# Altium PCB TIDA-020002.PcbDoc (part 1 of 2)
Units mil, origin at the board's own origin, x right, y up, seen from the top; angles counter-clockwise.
Board outline 1055.12 x 1877.5 mil, 6 copper layers (Layer 1 - Top Layer, Layer 2 - GND, Layer 3 - PWR, Layer 4 - Signal, Layer 5 - Signal/Gnd, Layer 6 - Bottom Layer), stack 62.2 mil thick; 103 components, 53 nets, 368 pads, 137 vias.
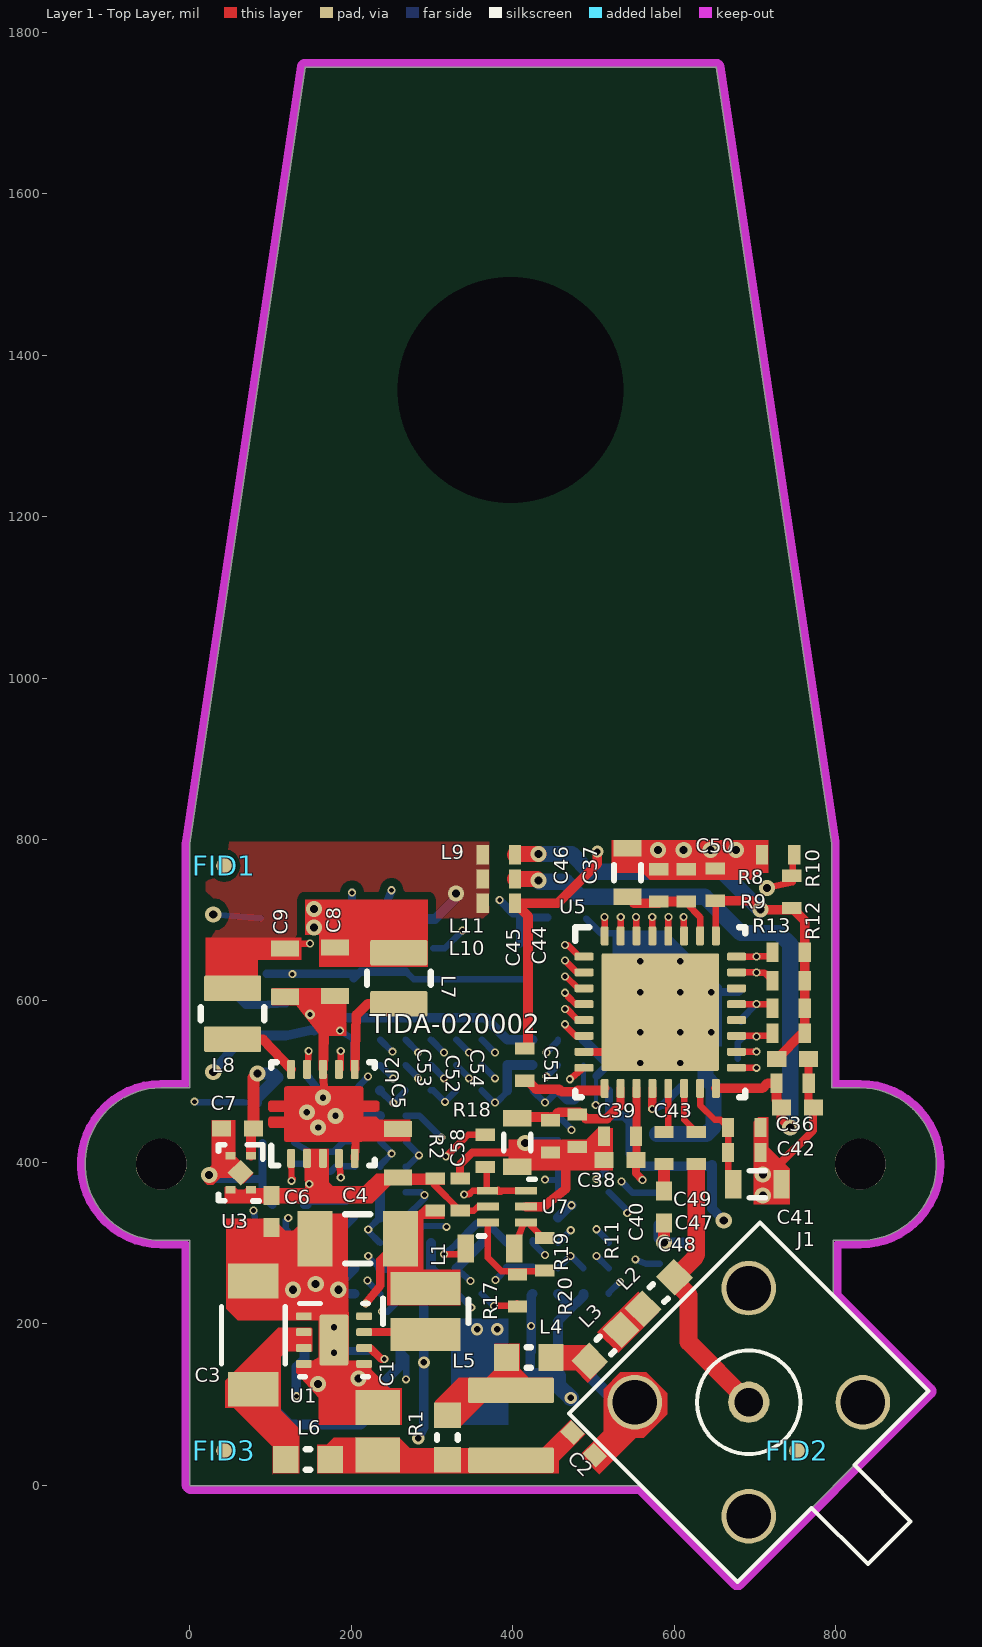
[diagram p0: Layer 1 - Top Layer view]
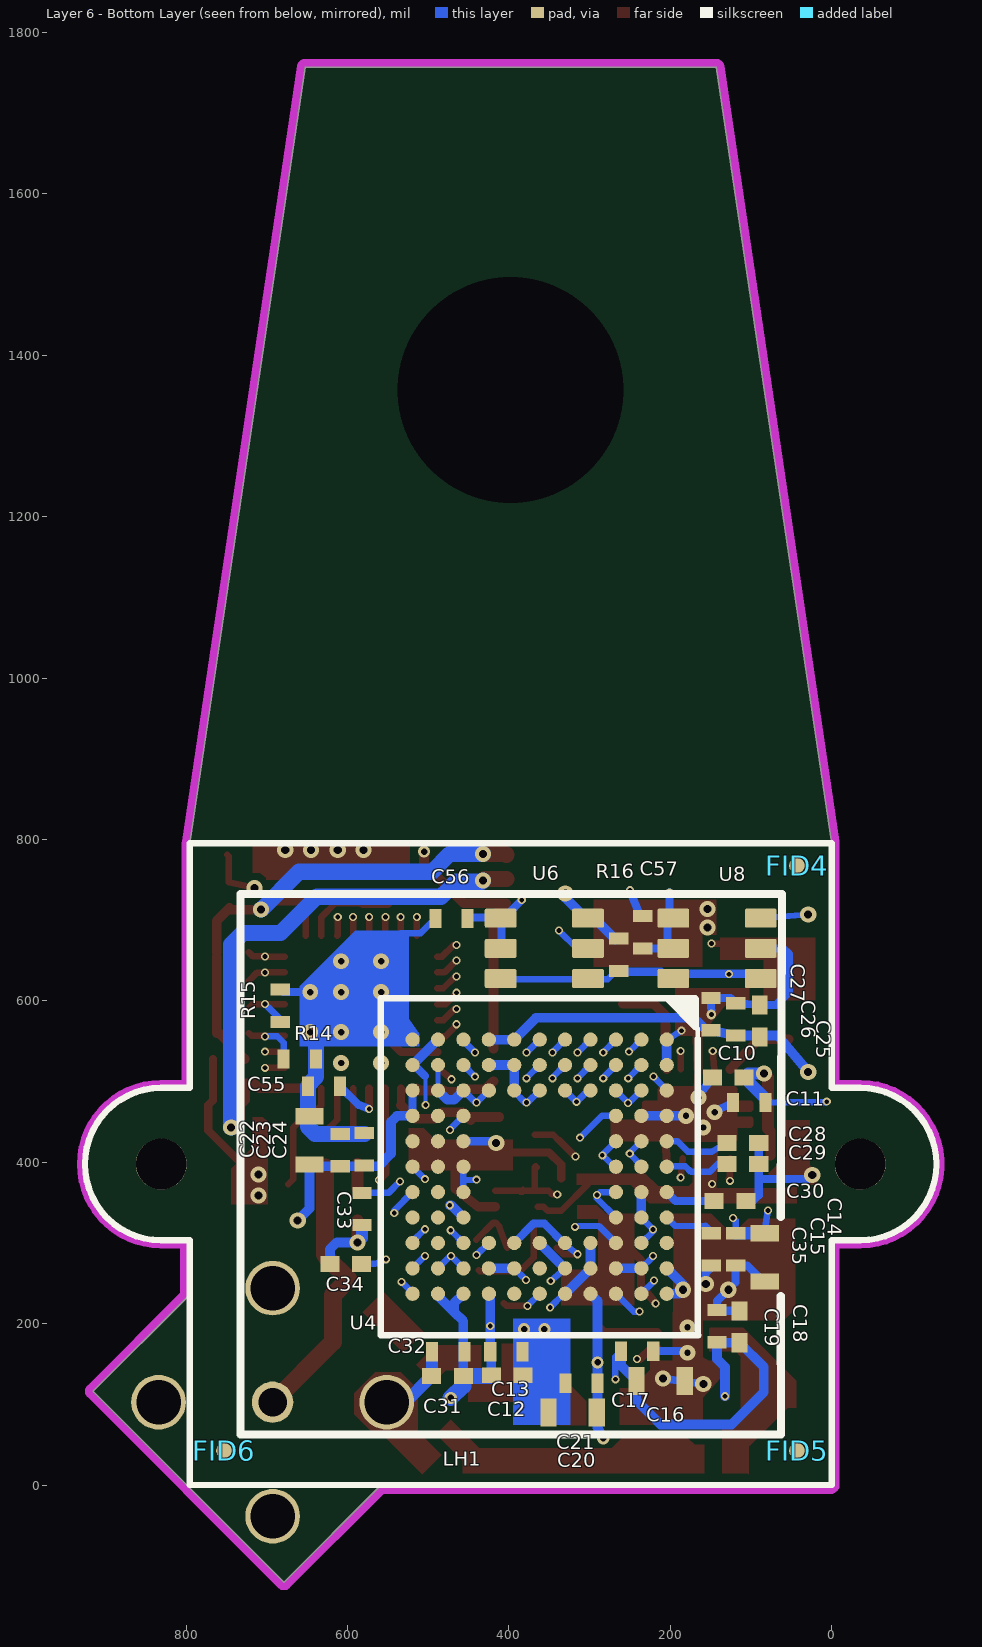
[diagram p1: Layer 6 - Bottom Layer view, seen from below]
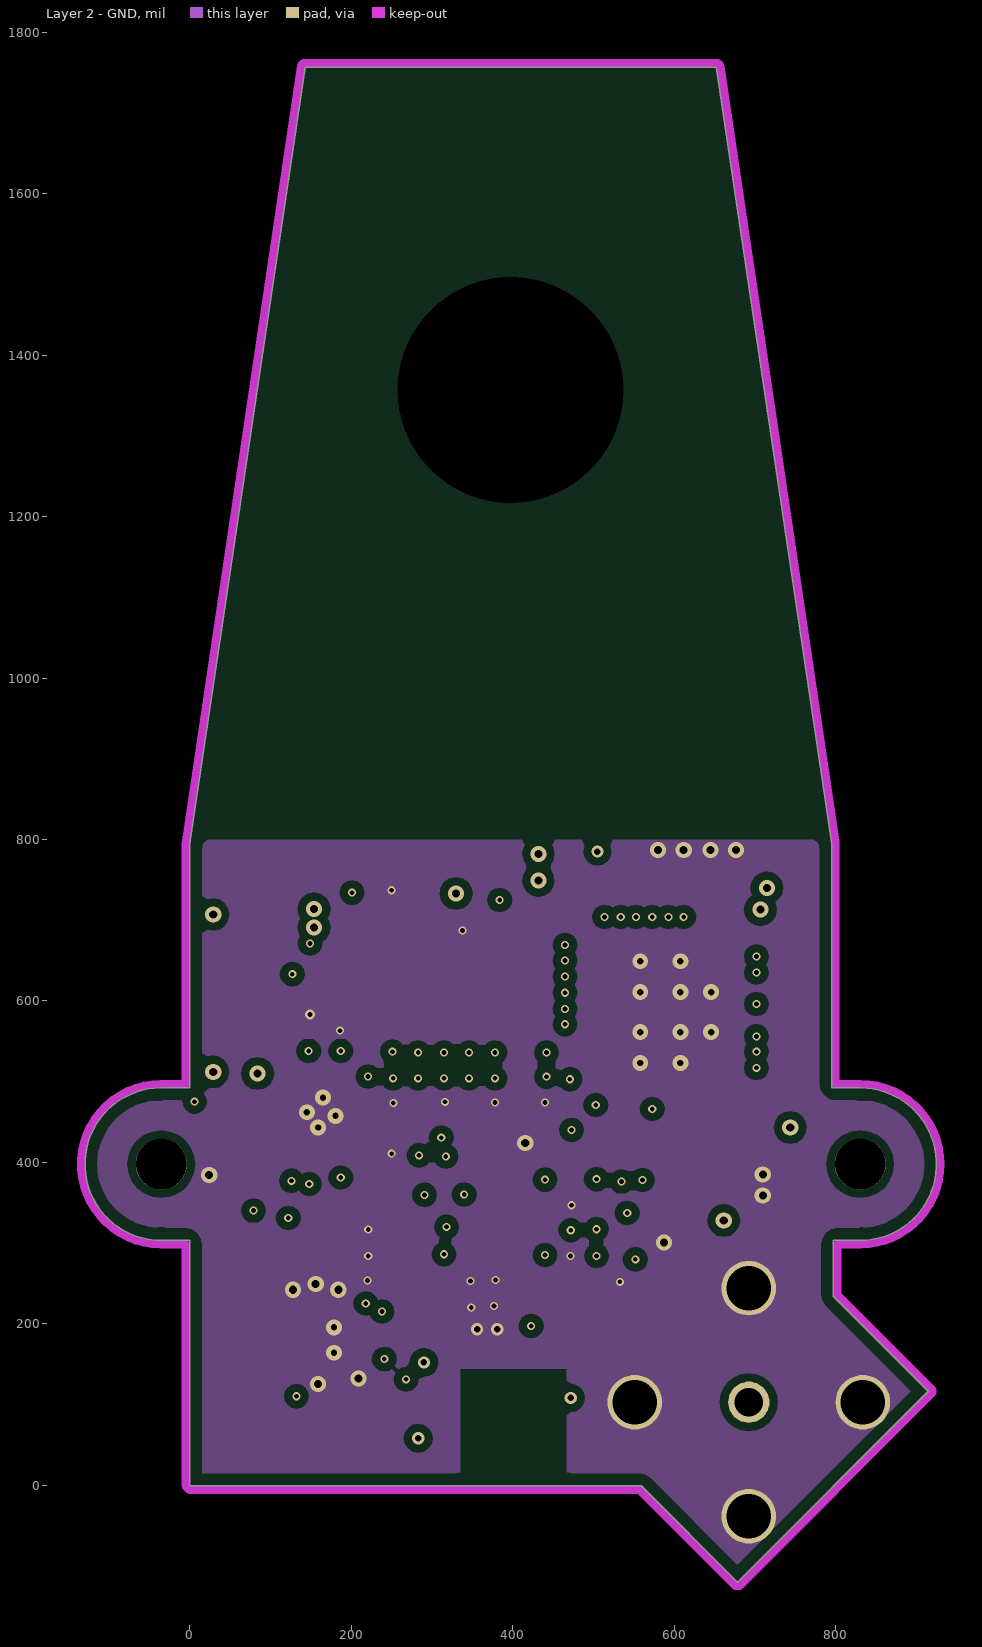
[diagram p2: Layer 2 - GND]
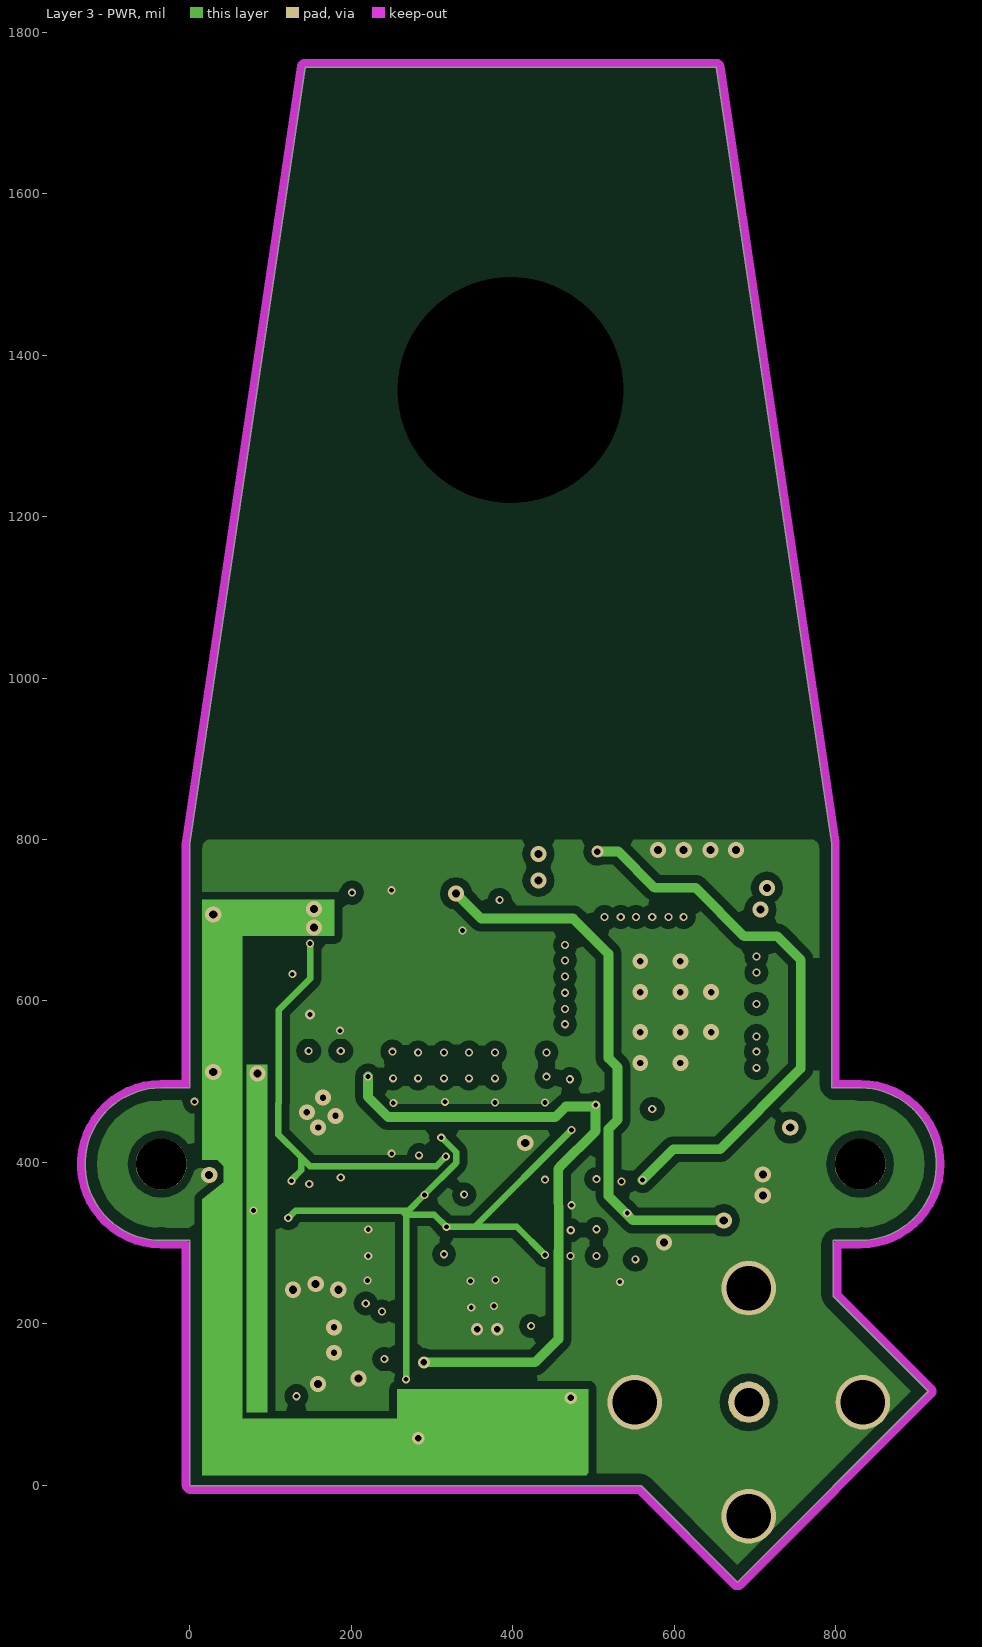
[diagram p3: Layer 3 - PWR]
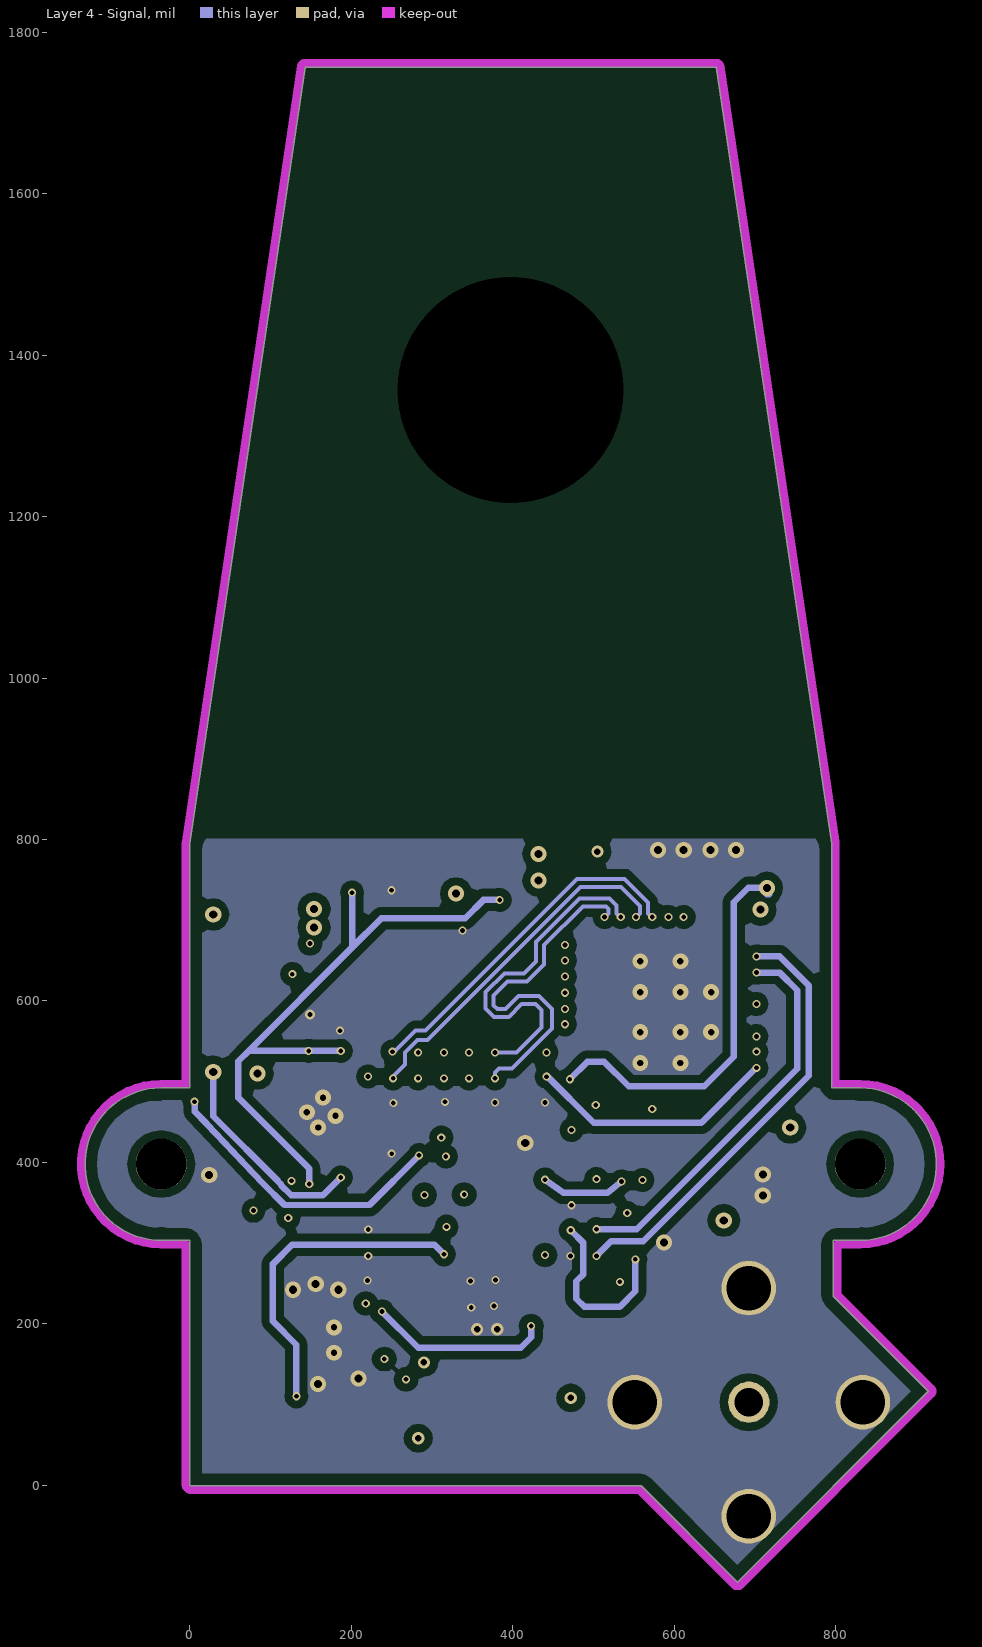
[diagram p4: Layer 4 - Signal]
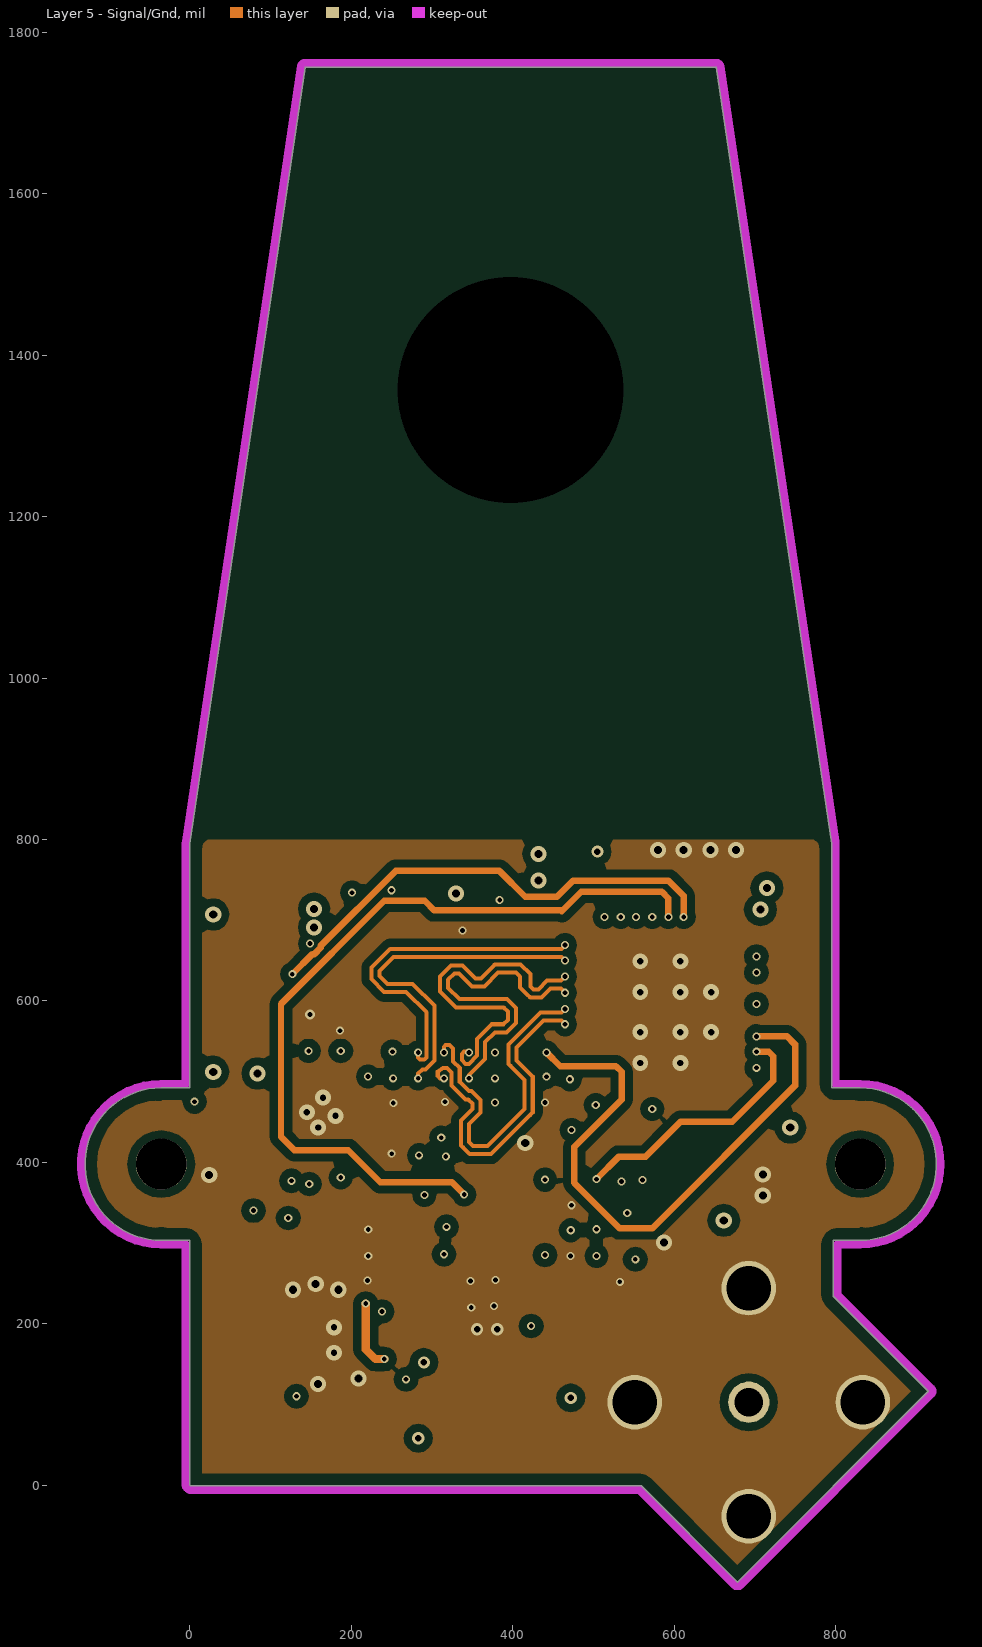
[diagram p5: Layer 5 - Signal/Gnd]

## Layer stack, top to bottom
Top Solder: solder mask 0.4, Solder Resist, Dk 3.5
Layer 1 - Top Layer: signal copper 1.4
Dielectric 1: prepreg 12.6, 370HR, Dk 4.2
Layer 2 - GND: signal copper 1.4
Dielectric 2: core 8, 370HR, Dk 4.2
Layer 3 - PWR: signal copper 1.4
Dielectric 5: prepreg 12.6, 370HR, Dk 4.2
Layer 4 - Signal: signal copper 1.4
Dielectric 4: core 8, 370HR, Dk 4.2
Layer 5 - Signal/Gnd: signal copper 1.4
Dielectric 3: prepreg 12.6, 370HR, Dk 4.2
Layer 6 - Bottom Layer: signal copper 1.4
Bottom Solder: solder mask 0.4, Solder Resist, Dk 3.5

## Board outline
-35.43,303.15 0,303.15 0,0 0.99,-0.99 559.27,-0.99 678.64,-120.36 915.14,116.14 797.27,234.01 797.27,303.15 830.71,303.15 ccw(c830.71,397.64) 830.71,492.13 795.28,492.13 795.28,795.28 795.28,794.64 652.39,1757.14 142.89,1757.14 0,794.64 0,795.28 0,492.13 -35.43,492.13 ccw(c-35.43,397.64)

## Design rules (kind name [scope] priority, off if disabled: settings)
AcuteAngle [All] p1 off: minimum=4.50000000000000E+0001 checktracksonly=FALSE
AssemblyTestPointUsage [All] p1: valid=2
Clearance Clearance_BoardEdge_MountingHoles [OnCopper and InComponentClass('Mounting Holes') vs IsKeepOut] p1 off: gap=30 ignorepadtopadclearanceinfootprint=FALSE except(0: Arc-Hole Track-Hole SMDPad-Hole THPad-Hole Via-Hole Fill-Hole Poly-Hole Region-Hole Text-Hole)
Clearance Clearance_BoardEdge_Poly [OnCopper and InPoly vs IsKeepOut] p2: gap=15 ignorepadtopadclearanceinfootprint=FALSE except(0: Arc-Hole Track-Hole SMDPad-Hole THPad-Hole Via-Hole Fill-Hole Poly-Hole Region-Hole Text-Hole)
Clearance Clearance_BoardEdge [OnCopper and Not InComponentClass('Logo') and not InComponentClass('FiducialMark') and not InRegion(1000,500,4000,800) and Not IsKeepout vs IsKeepOut and Not OnLayer('Keep-out Layer')] p3: gap=11 ignorepadtopadclearanceinfootprint=FALSE except(0: Arc-Hole Track-Hole SMDPad-Hole THPad-Hole Via-Hole Fill-Hole Poly-Hole Region-Hole Text-Hole)
Clearance Clearance_Poly [InPolygon] p4: gap=10 ignorepadtopadclearanceinfootprint=FALSE except(0: Arc-Hole Track-Hole SMDPad-Hole THPad-Hole Via-Hole Fill-Hole Poly-Hole Region-Hole Text-Hole)
Clearance [All] p5: gap=4 ignorepadtopadclearanceinfootprint=FALSE except(0: Arc-Hole Track-Hole SMDPad-Hole THPad-Hole Via-Hole Fill-Hole Poly-Hole Region-Hole Text-Hole)
ComponentClearance ComponentClearance_1 [issmtcomponent] p1: gap=0 collisioncheckmode=3 verticalgap=0 showdistances=FALSE
ComponentClearance ComponentClearance_Shunt [InComponentClass('Header') vs InComponentClass('Shunt')] p2: gap=0 collisioncheckmode=3 verticalgap=0 showdistances=FALSE
ComponentClearance ComponentClearance_Logo [InComponentClass('Logo')] p3: gap=0 collisioncheckmode=3 verticalgap=0 showdistances=FALSE
ComponentClearance ComponentClearance_ScrewToNut [(HasFootprint('NY PMS 440 0025 PH')) vs (HasFootprint('Keystone_1902C'))] p4: gap=5 collisioncheckmode=3 verticalgap=10 showdistances=FALSE
ComponentClearance ComponentClearance_MountingHoles [InComponentClass('Mounting Holes')] p5: gap=50 collisioncheckmode=3 verticalgap=50 showdistances=FALSE
ComponentClearance ComponentClearance_SmallPassives [HasFootprint('0201*') or HasFootprint('0402*') or HasFootprint('0508') or HasFootprint('0603*') or HasFootprint('0612') or HasFootprint('0805*') or HasFootprint('0815*') or HasFootprint('0830*') or HasFootprint('1206*') or HasFootprint('1210*') or HasFootprint('1808*') or HasFootprint('1812*') or HasFootprint('1825*') or HasFootprint('2010*') or HasFootprint('2220*') or HasFootprint('2225*') or HasFootprint('2512*') or HasFootprint('2728*') or HasFootprint('3518*') vs HasFootprint('0201*') or HasFootprint('0402*') or HasFootprint('0508') or HasFootprint('0603*') or HasFootprint('0612') or HasFootprint('0805*') or HasFootprint('0815*') or HasFootprint('0830*') or HasFootprint('1206*') or HasFootprint('1210*') or HasFootprint('1808*') or HasFootprint('1812*') or HasFootprint('1825*') or HasFootprint('2010*') or HasFootprint('2220*') or HasFootprint('2225*') or HasFootprint('2512*') or HasFootprint('2728*') or HasFootprint('3518*')] p6: gap=0 collisioncheckmode=3 verticalgap=0 showdistances=FALSE
ComponentClearance ComponentClearance_THtoSMT [IsThruComponent vs IsSMTComponent] p7: gap=0 collisioncheckmode=3 verticalgap=0 showdistances=FALSE
ComponentClearance ComponentClearance_THtoTH [IsThruComponent vs IsThruComponent] p8: gap=0 collisioncheckmode=3 verticalgap=0 showdistances=FALSE
ComponentClearance [All] p9: gap=0 collisioncheckmode=3 verticalgap=0 showdistances=FALSE
DiffPairsRouting DiffPair_Diff100_DiffPairsRouting [InDifferentialPairClass('Diff100')] p1: maxlimit=8 minlimit=5 mostfreqgap=8 toplayer_mingap=8 toplayer_minwidth=8 toplayer_maxwidth=8 toplayer_prefwidth=8 midlayer1_mingap=8 midlayer1_minwidth=8 midlayer1_maxwidth=8 midlayer1_prefwidth=8 midlayer2_mingap=8 midlayer2_minwidth=8 midlayer2_maxwidth=8 midlayer2_prefwidth=8 midlayer3_maxgap=5 midlayer3_prefgap=5 midlayer3_minwidth=5 midlayer3_maxwidth=5 midlayer3_prefwidth=5 midlayer4_maxgap=5 midlayer4_prefgap=5 midlayer4_minwidth=5 midlayer4_maxwidth=5 midlayer4_prefwidth=5 bottomlayer_mingap=8 bottomlayer_minwidth=8 bottomlayer_maxwidth=8 bottomlayer_prefwidth=8 maxuncoupledlength=500
DiffPairsRouting [All] p2: maxlimit=5 minlimit=5 mostfreqgap=5 toplayer_minwidth=5 toplayer_maxwidth=15 toplayer_prefwidth=8 midlayer1_minwidth=5 midlayer1_maxwidth=15 midlayer1_prefwidth=8 midlayer2_minwidth=5 midlayer2_maxwidth=15 midlayer2_prefwidth=8 midlayer3_minwidth=5 midlayer3_maxwidth=15 midlayer3_prefwidth=8 midlayer4_minwidth=5 midlayer4_maxwidth=15 midlayer4_prefwidth=8 bottomlayer_minwidth=5 bottomlayer_maxwidth=15 bottomlayer_prefwidth=8 maxuncoupledlength=1000
FabricationTestPointUsage TestPointUsage [All] p1: valid=2 allowmultiple=FALSE
FabricationTestpoint Testpoint [All] p1: side=3 testpointundercomponent=TRUE minsize=40 maxsize=100 preferedsize=60 minholesize=0 maxholesize=40 preferedholesize=32 testpointgrid=1 allowsidetop=TRUE allowsidebottom=TRUE usegrid=TRUE gridtolerance=0.01
FanoutControl Fanout_LCC [IsLCC] p1: bgadir=Out bgaviamode=Centered fanoutstyle=Auto fanoutdirection=Alternating viagrid=1 // Fanout_LCC (Default Rule)
FanoutControl Fanout_BGA [IsBGA] p2: bgadir=Out bgaviamode=Centered fanoutstyle=Auto fanoutdirection=Alternating viagrid=1 // Fanout_BGA (Default Rule)
FanoutControl Fanout_Default [All] p4: bgadir=Out bgaviamode=Centered fanoutstyle=Auto fanoutdirection=Alternating viagrid=1 // Fanout_Default (Default Rule)
FanoutControl Fanout_Small [(CompPinCount < 5)] p5: bgadir=Out bgaviamode=Centered fanoutstyle=Auto fanoutdirection=OutThenIn viagrid=1 // Fanout_Small (Default Rule)
HoleSize [All] p1: absolutevalues=TRUE maxlimit=280 minlimit=6 maxpercent=80.000 minpercent=20.000
MatchedLengths DiffPair_Diff100_MatchedLengths [InDifferentialPairClass('Diff100')] p1: tolerance=25 checknetsindiffpair=FALSE checkdiffpairvsdiffpair=TRUE checkxsignals=TRUE checkothers=TRUE
MinimumAnnularRing MinimumAnnularRing_ThermalPadVias [IsVia and InAnyComponent] p1: minimumring=5.91
MinimumAnnularRing [All] p2: minimumring=2
MinimumSolderMaskSliver MinimumSolderMaskSliver_Logo [InComponentClass('Logo') vs InComponentClass('Logo')] p1: minsoldermaskwidth=0.7
MinimumSolderMaskSliver [All] p2: minsoldermaskwidth=3.94
PlaneConnect [All] p1: planeconnectstyle=Relief reliefexpansion=10 reliefentries=4 reliefconductorwidth=10 reliefairgap=10
PolygonConnect [All] p1: connectstyle=Direct reliefconductorwidth=10 reliefentries=4 polygonreliefangle="90 Angle" airgapwidth=10
RoutingVias ThermalPadVias [IsVia and InAnyComponent] p1: holewidth=7.87 width=19.68 viastyle="Through Hole" minholewidth=7.87 minwidth=19.68 maxholewidth=12.99 maxwidth=23.62
RoutingVias [All] p2: holewidth=10 width=22 viastyle="Through Hole" minholewidth=6 minwidth=10 maxholewidth=40 maxwidth=65
SMDToCorner [All] p1: distance=25000
SilkToSilkClearance [All] p1: silktosilkclearance=0
SilkToSolderMaskClearance SilkscreenOverComponentPads [IsPad] p1: minsilkscreentomaskgap=0.2 clearancetoexposedcopper=TRUE
SolderMaskExpansion [All] p1: expansion=1
Width [All] p1: maxlimit=100 minlimit=5 preferedwidth=10 minimp=50.000000 maximp=50.000000 favimp=50.000000 checkconnectedcopper=TRUE
16 further rules are at their usual default settings.

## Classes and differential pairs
component class "Voltage Supervision": C56 C57 C58 R16 R17 R18 R19 R20 U6 U7 U8
differential pair class Diff100: CSI0_CLK CSI0_D0 CSI0_D1 CSI0_D2 CSI0_D3
component class Serializer: C36 C37 C38 C39 C40 C41 C42 C43 C44 C45 C46 C47 C48 C49 C50 C51 C52 C53 C54 C55 L9 L10 L11 R8 R9 R10 R11 R12 R13 R14 R15 U5
component class "Coax Connection and Power Supply": C1 C2 C3 C4 C5 C6 C7 C8 C9 J1 L1 L2 L3 L4 L5 L6 L7 L8 R1 R2 U1 U2 U3
component class Imager: C10 C11 C12 C13 C14 C15 C16 C17 C18 C19 C20 C21 C22 C23 C24 C25 C26 C27 C28 C29 C30 C31 C32 C33 C34 C35 R23 U4
component class AssemblyNote: ZZ1 ZZ2 ZZ3
component class FiducialMark: FID1 FID2 FID3 FID4 FID5 FID6
component class HDWR: FID1 FID2 FID3 FID4 FID5 FID6 LH1 ZZ1 ZZ2 ZZ3
differential pair CSI0_CLK: +CSI0_CLK_P -CSI0_CLK_N
differential pair CSI0_D0: +CSI0_D0_P -CSI0_D0_N
differential pair CSI0_D1: +CSI0_D1_P -CSI0_D1_N
differential pair CSI0_D2: +CSI0_D2_P -CSI0_D2_N
differential pair CSI0_D3: +CSI0_D3_P -CSI0_D3_N

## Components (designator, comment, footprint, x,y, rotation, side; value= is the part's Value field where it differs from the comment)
C1 "CGA4J1X7R1E475M125AC" 0805L 232.64,66.64 r90 top value=4.7µF
C2 "C1005X7R1E104K050BB" 0402L 488,51 r315 top value=0.1µF
C3 "C3216X7R1E106M160AE" 1206_190 78.64,185.64 r90 top value=10uF
C4 "GRM31CR71A226KE15L" 1206L 208,305 r180 top value=22uF
C5 "GRM188Z71A106MA73D" 0603S 258,411 r90 top value=10uF
C6 "CL05B105KQ5NQNC" 0402L 101,339 r270 top value=1.0µF
C7 "CL05B105KQ5NQNC" 0402L 59,442 r180 top value=1.0µF
C8 "GRM188Z71A106MA73D" 0603S 180,636 r270 top value=10uF
C9 "GRM188Z71A106MA73D" 0603S 118,635 r270 top value=10uF
C10 "CL05B105KQ5NQNC" 0402L 128,505 r0 bottom value=1.0µF
C11 "0402YC104KAT2A" 0402S 102,474 r0 bottom value=0.1uF
C12 "CL05B105KQ5NQNC" 0402L 402,136 r180 bottom value=1.0µF
C13 "0402YC104KAT2A" 0402S 403,165 r180 bottom value=0.1uF
C14 "GRM188Z71C475KE21D" 0603S 83,282 r270 bottom value=4.7uF
C15 "0402YC104KAT2A" 0402S 119,292 r270 bottom value=0.1uF
C16 "GRM188Z71C475KE21D" 0603S 212,129 r180 bottom value=4.7uF
C17 "0402YC104KAT2A" 0402S 241,166 r180 bottom value=0.1uF
C18 "CL05B105KQ5NQNC" 0402L 114,196 r90 bottom value=1.0µF
C19 "0402YC104KAT2A" 0402S 142,197 r90 bottom value=0.1uF
C20 "GRM188Z71C475KE21D" 0603S 321,90 r0 bottom value=4.7uF
C21 "0402YC104KAT2A" 0402S 310,126 r0 bottom value=0.1uF
C22 "GRM188Z71C475KE21D" 0603S 647,427 r90 bottom value=4.7uF
C23 "0402YC104KAT2A" 0402S 609,415 r90 bottom value=0.1uF
C24 "GRM155R70J103KA01D" 0402S 579,416 r90 bottom value=0.01uF
C25 "CL05B105KQ5NQNC" 0402L 89,575 r90 bottom value=1.0µF
C26 "0402YC104KAT2A" 0402S 119,577 r90 bottom value=0.1uF
C27 "GRM155R70J103KA01D" 0402S 149.5,583.5 r90 bottom value=0.01uF
C28 "CL05B105KQ5NQNC" 0402L 110,424 r180 bottom value=1.0µF
C29 "CL05B105KQ5NQNC" 0402L 110,398 r180 bottom value=1.0µF
C30 "CL05B105KQ5NQNC" 0402L 126,352 r180 bottom value=1.0µF
C31 "CL05B105KQ5NQNC" 0402L 476,135 r0 bottom value=1.0µF
C32 "0402YC104KAT2A" 0402S 475,165 r0 bottom value=0.1uF
C33 "GRM155R71A224KE01D" 0402S 582,342 r270 bottom value=0.22uF
C34 "CL05B105KQ5NQNC" 0402L 602,274 r0 bottom value=1.0µF
C35 "0402YC104KAT2A" 0402S 149,292 r270 bottom value=0.1uF
C36 "CL05B105KQ5NQNC" 0402L 747,528 r0 top value=1.0µF
C37 "GRM155R71C103KA01D" 0402S 651,744 r90 top value=0.01uF
C38 "CL05B105KQ5NQNC" 0402L 533,403 r180 top value=1.0µF
C39 "GRM155R71C103KA01D" 0402S 533,432 r180 top value=0.01uF
C40 "CGA2B3X7R1H333K050BB" 0402S 627.64,417.64 r90 top value=0.033uF
C41 "CL05B105KQ5NQNC" 0402L 753,468 r0 top value=1.0µF
C42 "GRM155R71C103KA01D" 0402S 747,498 r0 top value=0.01uF
C43 "CGA2B3X7R1H153K050BB" 0402S 587.64,417.64 r90 top value=0.015uF
C44 "0402YC104KAT2A" 0402S 581,743 r90 top value=0.1uF
C45 "GRM188Z71A106MA73D" 0603S 542.39,759 r270 top value=10uF
C46 "GRM155R71C103KA01D" 0402S 615,743 r90 top value=0.01uF
C47 "0402YC104KAT2A" 0402S 687,412 r0 top value=0.1uF
C48 "GRM188Z71A106MA73D" 0603S 703.39,372.64 r180 top value=10uF
C49 "GRM155R71C103KA01D" 0402S 687,443 r0 top value=0.01uF
C50 "GRM155R70J105MA12D" 0402S 729,781 r180 top value=1uF
C51 "GRM155R70J223KA01D" 0402S 415,521 r270 top value=0.022uF
C52 "0402YC104KAT2A" 0402S 447,432 r270 top value=0.1uF
C53 "GRM188Z71A106MA73D" 0603S 405.63,424.46 r90 top value=10uF
C54 "GRM155R71C103KA01D" 0402S 480,439 r270 top value=0.01uF
C55 "0402YC104KAT2A" 0402S 629,494 r0 bottom value=0.1uF
C56 "GRM155R71A104KA01D" 0402S 471,702 r0 bottom value=0.1uF
C57 "GRM155R71A104KA01D" 0402S 234,685 r90 bottom value=0.1uF
C58 "GRM155R71A104KA01D" 0402S 335,360 r90 top value=0.1uF
FID1 "Fiducial" Fiducial10-20 42.64,767.64 r0 top
FID2 "Fiducial" Fiducial10-20 752.64,42.64 r0 top
FID3 "Fiducial" Fiducial10-20 42.64,42.64 r0 top
FID4 "Fiducial" Fiducial10-20 42.64,767.64 r90 bottom
FID5 "Fiducial" Fiducial10-20 42.64,42.64 r90 bottom
FID6 "Fiducial" Fiducial10-20 752.64,42.64 r90 bottom
J1 "59S10H-40ML5-Y" 59S10H-40ML5-Y 692.64,102.64 r315 top locked
L1 "XPL2010-332MLB" XPL2010 292,215 r90 top value=3.3uH
L2 "BLM18HE152SN1D" 0603L 581,238 r225 top value="1500 ohm"
L3 "BLM18HE152SN1D" 0603L 515,173 r225 top value="1500 ohm"
L4 "BLM18HE152SN1D" 0603L 420,158 r180 top value="1500 ohm"
L5 "LQH3NPZ100MJRL" LQH3NPZ_JR 398,74 r90 top value=10uH
L6 "BLM18AG102SN1D" 0603L 146.64,31.64 r180 top value="1000 ohm"
L7 "LQM2MPN2R2NG0" LQM2MPN_G0 259,628 r90 top value=2.2uH
L8 "LQM2MPN2R2NG0" LQM2MPN_G0 53,584 r90 top value=2.2uH
L9 "BLM15AX102SN1D" 0402S 383,781 r0 top value="1000 ohm"
L10 "BLM15AX102SN1D" 0402S 383,721 r0 top value="1000 ohm"
L11 "BLM15AX102SN1D" 0402S 383,751 r0 top value="1000 ohm"
LH1 "CMT821" CMT821 397.64,397.64 r180 bottom locked
R1 "CRCW06034K02FKEA" 0603L 319,59 r90 top value=4.02k
R2 "CRCW04020000Z0ED" 0402S 304,360 r270 top value=0
R8 "CRCW04021K50JNED" 0402S 742,660 r0 top value=1.5k
R9 "CRCW04021K50JNED" 0402S 742,625 r0 top value=1.5k
R10 "CRCW040210K0JNED" 0402S 746,735 r270 top value=10k
R11 "CRCW040249R9FKED" 0402L 587.64,344.64 r90 top value=49.9
R12 "DNP" 0402S 742,560 r0 top value=0
R13 "CRCW040210K0JNED" 0402S 742,591 r0 top value=10k
R14 "CRCW040240K2FKED" 0402S 659,528 r0 bottom value=40.2k
R15 "CRCW0402402RFKED" 0402S 683,594 r270 bottom value=402
R16 "CRCW040220K0FKED" 0402S 264,657 r90 bottom value=20.0k
R17 "RT0603BRD07556KL" 0603S 372,293 r180 top value=556k
R18 "CRCW040220K0FKED" 0402S 366,414 r90 top value=20.0k
R19 "PNM0402E5001BST1" 0402S 440,286 r90 top value=5.00k
R20 "ERA-2AEB8662X" 0402S 406,241 r90 top value=86.6k
U1 "TPS62162QDSGRQ1" DSG0008A 178.64,179.64 r0 top
U2 "TPS62423QDRCRQ1" DRC0010J 165,460 r90 top
U3 "LP5907SNX-2.9/NOPB" DQN0004A 63,387 r270 top
U4 "IMX390CQV-W" BGA-96 361.75,394.49 r270 bottom locked
U5 "DS90UB953TRHBRQ1" RHB0032P 583,586 r0 top
U6 "TPS3702CX18QDDCRQ1" DDC0006A_N 356,665 r0 bottom
U7 "TPS3700QDSERQ1" DSE0006A 393,345 r0 top
U8 "TPS3702CX12QDDCRQ1" DDC0006A_N 142,665 r0 bottom
ZZ1 "These assemblies are ESD sensitive, ESD precautions shall be observed." AssemblyNote 67.64,2097.64 r0 top
ZZ2 "These assemblies must be clean and free from flux and all contaminants. Use of no clean flux is not acceptable." AssemblyNote 67.64,1997.64 r0 top
ZZ3 "These assemblies must comply with workmanship standards IPC-A-610 Class 2, unless otherwise specified." AssemblyNote 67.64,1897.64 r0 top

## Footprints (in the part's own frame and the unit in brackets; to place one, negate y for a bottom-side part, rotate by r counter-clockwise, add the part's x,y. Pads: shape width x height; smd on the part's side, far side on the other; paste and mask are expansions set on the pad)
59S10H-40ML5-Y [mm] "Rosenberger Straight Plug"
  round 1.3 hole 0.9 mask+0: 1(0,0)
  round 1.72 hole 1.4 mask+0: 2(-2.54,2.54) 3(-2.54,-2.54) 4(2.54,-2.54) 5(2.54,2.54)
  silkscreen extent -3.75,-4.25 6.25,4.25
0402L [mm] "0402 from SM-752 data"
  rect 0.6x0.5 smd: 1(-0.5,0) 2(0.5,0)
  body extent -0.55,-0.3 0.55,0.3, height 0.6
0402S [mil] "Based on C0402S footprint from PADS legacy"
  rect 15x24 smd: 1(-20,0) 2(20,0)
  body extent -22,-12 22,12, height 24
0603L [mm] "0603 from SM-752 data"
  rect 0.8x0.85 smd: 1(-0.7,0) 2(0.7,0)
  silkscreen extent -0.07,-0.32 0.07,0.32, body extent -0.87,-0.47 0.87,0.47, height 1
0603S [mil]
  rect 20x35 smd: 1(-30,0) 2(30,0)
  body extent -34,-19 34,19, height 39
0805L [mm] "0805 from SM-752 data"
  rect 1.1x1.4 smd: 1(-0.75,0) 2(0.75,0)
  body extent -1.1,-0.72 1.1,0.72, height 1.1
1206_190 [mm] "1206_190"
  rect 1.1x1.6 smd: 1(-1.7,0) 2(1.7,0)
  silkscreen extent -0.9,-1 0.9,1, body extent -1.75,-0.95 1.75,0.95, height 1.9
1206L [mm] "1206 from SM-752 data"
  rect 1.1x1.75 smd: 1(-1.35,0) 2(1.35,0)
  silkscreen extent -0.4,-0.77 0.4,0.77, body extent -1.7,-0.9 1.7,0.9, height 1.35
AssemblyNote [mil] "Assembly Note"
BGA-96 [mm] "BGA, 96-Balls, Body 10.6x10mm, Pitch 0.8mm"
  round 0.45 smd: A1(-4,4) A2(-3.2,4) A3(-2.4,4) A4(-1.6,4) A5(-0.8,4) A6(0,4) A7(0.8,4) A8(1.6,4) A9(2.4,4) A10(3.2,4) A11(4,4) B1(-4,3.2) B2(-3.2,3.2) B3(-2.4,3.2) B4(-1.6,3.2) B5(-0.8,3.2) B6(0,3.2) B7(0.8,3.2) B8(1.6,3.2) B9(2.4,3.2) B10(3.2,3.2) B11(4,3.2) C1(-4,2.4) C2(-3.2,2.4) C3(-2.4,2.4) C4(-1.6,2.4) C5(-0.8,2.4) C6(0,2.4) C7(0.8,2.4) C8(1.6,2.4) C9(2.4,2.4) C10(3.2,2.4) C11(4,2.4) D1(-4,1.6) D2(-3.2,1.6) D3(-2.4,1.6) D9(2.4,1.6) D10(3.2,1.6) D11(4,1.6) E1(-4,0.8) E2(-3.2,0.8) E3(-2.4,0.8) E9(2.4,0.8) E10(3.2,0.8) E11(4,0.8) F1(-4,0) F2(-3.2,0) F3(-2.4,0) F9(2.4,0) F10(3.2,0) F11(4,0) G1(-4,-0.8) G2(-3.2,-0.8) G3(-2.4,-0.8) G9(2.4,-0.8) G10(3.2,-0.8) G11(4,-0.8) H1(-4,-1.6) H2(-3.2,-1.6) H3(-2.4,-1.6) H9(2.4,-1.6) H10(3.2,-1.6) H11(4,-1.6) J1(-4,-2.4) J2(-3.2,-2.4) J3(-2.4,-2.4) J4(-1.6,-2.4) J5(-0.8,-2.4) J6(0,-2.4) J7(0.8,-2.4) J8(1.6,-2.4) J9(2.4,-2.4) J10(3.2,-2.4) J11(4,-2.4) K1(-4,-3.2) K2(-3.2,-3.2) K3(-2.4,-3.2) K4(-1.6,-3.2) K5(-0.8,-3.2) K6(0,-3.2) K7(0.8,-3.2) K8(1.6,-3.2) K9(2.4,-3.2) K10(3.2,-3.2) K11(4,-3.2) L1(-4,-4) L2(-3.2,-4) L3(-2.4,-4) L4(-1.6,-4) L5(-0.8,-4) L6(0,-4) L7(0.8,-4) L8(1.6,-4) L9(2.4,-4) L10(3.2,-4) L11(4,-4)
  silkscreen extent -5.3,-5 5.3,5, body extent -5.3,-5 5.3,5, height 1.6
CMT821 [mm] "SUNEX Lens Holder"
  round 1.6 hole 1.6 unplated paste+0: MT1(-11,0) MT2(11,0)
  M6 Assembly Bottom keep-out lines w0.2: 8.5,-8.5 8.5,8.5 -8.5,8.5 -8.5,-8.5 8.5,-8.5
  silkscreen extent -13.4,-10.1 13.4,10.1
DDC0006A_N [mm]
  rrect17% 1x0.6 smd: 1(-1.375,0.95) 2(-1.375,0) 3(-1.375,-0.95) 4(1.375,-0.95) 5(1.375,0) 6(1.375,0.95)
  body extent -1.43,-1.48 1.43,1.49, height 0.92
DQN0004A [mm] "SON, 0.65mm pitch"
  rect 0.25x0.31 smd paste-1 mask-0.31: 1(-0.535,0.325) 2(-0.535,-0.325) 3(0.535,-0.325) 4(0.535,0.325)
  rect 0.58x0.58 smd rot 45 paste-0.065 mask-0.05: 5(0,0)
  silkscreen extent -0.88,-0.7 0.89,0.7, body extent -0.53,-0.53 0.53,0.53, height 0.42
DRC0010J [mm] "SON, 10-Leads, Body 3x3mm, Pitch 0.5mm, Thermal Pad 2.4x1.65mm, TI Recommended"
  rrect40% 0.6x0.25 smd: 1(-1.4,1) 2(-1.4,0.5) 3(-1.4,0) 4(-1.4,-0.5) 5(-1.4,-1) 6(1.4,-1) 7(1.4,-0.5) 8(1.4,0) 9(1.4,0.5) 10(1.4,1)
  rrect40% 0.25x0.34 on Top Paste: 11(-0.25,1.53) 11(-0.25,-1.53) 11(0.25,1.53) 11(0.25,-1.53)
  rrect9% 1.5x1.06 on Top Paste: 11(0,0.63) 11(0,-0.63)
  Layer 1 - Top Layer region: -0.086,-1.675 -0.186,-1.778 -0.186,-2.754 -0.87,-2.754 -0.87,-1.231 -0.882,-1.204 -0.886,-1.175 -0.886,-1.175 -0.886,1.125 -0.879,1.163 -0.857,1.195 -0.825,1.217 -0.786,1.225 -0.786,1.225 -0.436,1.225 -0.436,1.625 -0.429,1.663 -0.407,1.695 -0.375,1.717 -0.336,1.725 -0.336,1.725 -0.186,1.725 -0.148,1.717 -0.116,1.695 -0.094,1.663 -0.086,1.625 -0.086,1.625 -0.086,1.225 0.064,1.225 0.064,1.625 0.071,1.663 0.093,1.695 0.125,1.717 0.164,1.725 0.164,1.725 0.314,1.725 0.352,1.717 0.384,1.695 0.406,1.663 0.414,1.625 0.414,1.625 0.414,1.225 0.764,1.225 0.802,1.217 0.834,1.195 0.856,1.163 0.864,1.125 0.864,1.125 0.864,-1.175 0.856,-1.214 0.834,-1.246 0.802,-1.268 0.764,-1.275 0.764,-1.275 0.414,-1.275 0.414,-1.675 0.406,-1.714 0.384,-1.746 0.352,-1.768 0.314,-1.775 0.314,-1.775 0.164,-1.775 0.125,-1.768 0.093,-1.746 0.071,-1.714 0.064,-1.675 0.064,-1.675 0.064,-1.275 -0.086,-1.275
  silkscreen extent -1.63,-1.63 1.63,1.63, body extent -1.5,-1.5 1.5,1.5, height 0.77
DSE0006A [mm] "TI recommended land pattern"
  rect 0.66x0.25 smd: 1(-0.62,0.5)
  rect 0.7x0.25 smd: 2(-0.6,0) 3(-0.6,-0.5) 4(0.6,-0.5) 5(0.6,0) 6(0.6,0.5)
  Layer 1 - Top Layer region: -0.3,0.625 -0.25,0.625 -0.15,0.525 -0.15,0.375 -0.3,0.375
  silkscreen extent -0.9,-0.92 0.89,0.86, body extent -0.77,-0.77 0.77,0.77, height 0.8
DSG0008A [mm] "SON, 8-Leads, Body 2x2mm, Pitch 0.5mm, Thermal Pad 1.6x0.9mm, TI Recommended"
  rrect40% 0.5x0.25 smd: 1(-0.95,0.75) 2(-0.95,0.25) 3(-0.95,-0.25) 4(-0.95,-0.75) 5(0.95,-0.75) 6(0.95,-0.25) 7(0.95,0.25) 8(0.95,0.75)
  rrect11% 0.9x1.6 smd paste-0.45: 9(0,0)
  silkscreen extent -1.07,-1.15 1.07,1.15, body extent -1.05,-1.05 1.05,1.05, height 0.8
Fiducial10-20 [mil]
  round 20 smd paste-19.68 mask+19.68: 1(0,0)
LQH3NPZ_JR [mm] "SMD, 2-Leads, Body 3x3mm"
  rrect12% 0.8x2.7 smd: 1(-1.1,0) 2(1.1,0)
  body extent -1.6,-1.6 1.6,1.6, height 1.2
LQM2MPN_G0 [mm] "MuRata"
  rrect12% 0.8x1.8 smd: 1(-0.8,0) 2(0.8,0)
  silkscreen extent -0.2,-1 0.2,1, body extent -1.07,-0.87 1.07,0.87, height 1
RHB0032P [mm] "QFN, 32-Leads, Body 5x5mm, Pitch 0.5mm, Thermal Pad 3.7x3.7mm"
  rrect40% 0.6x0.25 smd: 1(-2.4,1.75) 2(-2.4,1.25) 3(-2.4,0.75) 4(-2.4,0.25) 5(-2.4,-0.25) 6(-2.4,-0.75) 7(-2.4,-1.25) 8(-2.4,-1.75) 17(2.4,-1.75) 18(2.4,-1.25) 19(2.4,-0.75) 20(2.4,-0.25) 21(2.4,0.25) 22(2.4,0.75) 23(2.4,1.25) 24(2.4,1.75)
  rrect40% 0.25x0.6 smd: 9(-1.75,-2.4) 10(-1.25,-2.4) 11(-0.75,-2.4) 12(-0.25,-2.4) 13(0.25,-2.4) 14(0.75,-2.4) 15(1.25,-2.4) 16(1.75,-2.4) 25(1.75,2.4) 26(1.25,2.4) 27(0.75,2.4) 28(0.25,2.4) 29(-0.25,2.4) 30(-0.75,2.4) 31(-1.25,2.4) 32(-1.75,2.4)
  rrect9% 1.06x1.06 on Top Paste: 33(-1.26,-1.26) 33(-1.26,0) 33(-1.26,1.26) 33(0,-1.26) 33(0,0) 33(0,1.26) 33(1.26,-1.26) 33(1.26,0) 33(1.26,1.26)
  rrect3% 3.7x3.7 smd paste-1.85: 33(0,0)
  silkscreen extent -2.67,-2.68 2.67,2.68, body extent -2.5,-2.5 2.5,2.5, height 1
XPL2010 [mm] "Coilcraft recommended land pattern Document 646-2 Revised 3/28/11"
  rect 1.04x2.2 smd: 1(-0.725,0) 2(0.725,0)
  silkscreen extent -0.4,-1.36 0.42,1.34, body extent -1.05,-1.1 1.05,1.1, height 1

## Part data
C1: library part C2012X7R1E474K, "CAP, CERM, 4.7uF, 25V, +/-20%, X7R, 0805", Manufacturer="TDK Corporation", Operating Temperature="-55°C ~ 125°C", Ratings=AEC-Q200, Supplier Part Number 1=445-12761-1-ND, TempCo=X7R, Tolerance_%=±20%
C2: library part C1005X7R1E103K, "CAP, CERM, 0.1uF, 25V, +/-10%, X7R, 0402", Manufacturer="TDK Corporation", Operating Temperature="-55°C ~ 125°C", Ratings=-, Supplier Part Number 1=445-7348-1-ND, TempCo=X7R, Tolerance_%=±10%
C3: "CAP, CERM, 10 µF, 25 V,+/- 20%, X7R, 1206", Cap_Case=1206, Manufacturer=TDK, Supplier Part Number 1=445-6812-1-ND, TempCo=X7R, Tolerance_%=20, Value2=25V, ValueDisplayed=10µF
C4: "CAP, CERM, 22uF, 10V, +/-10%, X7R, 1206", Cap_Case=1206, Manufacturer=MuRata, Supplier Part Number 1=490-5309-1-ND, TempCo=X7R, Tolerance_%=10, Value1=Unknown, Value2=10V, ValueDisplayed=22µF
C5 C8 C9: library part CMP-0007497-5, "CAP, CERM, 10 uF, 10 V, +/- 20%, X7R, 0603", Cap_Case=0603, Manufacturer=MuRata, Supplier Part Number 1=81-GRM188Z71A106MA3D, TempCo=X7R, Tolerance_%=20%, Value1=Unknown, Value2=10V, ValueDisplayed=10uF
C6 C7 C10 C12 C18 C25 C28 C29 C30 C31 C34 C36 C38 C41: library part Capacitor, "CAP CER 1UF 6.3V 10% X7R 0402", Alternate Manufacturer=-, Manufacturer="Samsung Electro-Mechanics America, Inc", Operating Temperature="-55°C ~ 125°C", Supplier Part Number 1=1276-1513-1-ND, TempCo=X7R, Tolerance_%=±10%
C11 C13 C15 C17 C19 C21 C23 C26 C32 C35 C44 C47 C52 C55: "CAP, CERM, 0.1 µF, 16 V, +/- 10%, X7R, 0402", Cap_Case=0402, Manufacturer=AVX, Supplier Part Number 1=478-7888-1-ND, TempCo=X7R, Tolerance_%=10, Value1=Unknown, Value2=16V, ValueDisplayed=0.1µF
C14 C16 C20 C22: library part CMP-0064936-4, "CAP, CERM, 4.7 uF, 16 V,+/- 10%, X7R, 0603", Cap_Case=0603, Manufacturer=MuRata, TempCo=X7R, Tolerance_%=10%, Value1=Unknown, Value2=16V, ValueDisplayed=4.7uF
C24 C27: library part CMP-0006622-2, "CAP, CERM, 0.01 uF, 6.3 V, +/- 10%, X7R, 0402", Cap_Case=0402, Manufacturer=MuRata, Supplier Part Number 1=GRM155R70J103KA01D-ND, TempCo=X7R, Tolerance_%=10%, Value1=Unknown, Value2=6.3V, ValueDisplayed=0.01uF
C33: library part CMP-0006630-2, "CAP, CERM, 0.22 uF, 10 V, +/- 10%, X7R, 0402", Cap_Case=0402, Manufacturer=MuRata, Supplier Part Number 1=490-12706-1-ND, TempCo=X7R, Tolerance_%=10%, Value1=Unknown, Value2=10V, ValueDisplayed=0.22uF
C37 C39 C42 C46 C49 C54: "CAP, CERM, 0.01uF, 16V, +/-10%, X7R, 0402", Cap_Case=0402, Manufacturer=MuRata, Supplier Part Number 1=490-1313-1-ND, TempCo=X7R, Tolerance_%=10, Value1=Unknown, Value2=16V, ValueDisplayed=0.01µF
C40: "CAP, CERM, 0.033 µF, 50 V, +/- 10%, X7R, 0402", Cap_Case=0402, Manufacturer=TDK, Supplier Part Number 1=445-6896-1-ND, TempCo=X7R, Tolerance_%=10, Value1=Unknown, Value2=50V, ValueDisplayed=0.033µF
C43: "CAP, CERM, 0.015 µF, 50 V, +/- 10%, X7R, AEC-Q200 Grade 1, 0402", Cap_Case=0402, Manufacturer=TDK, Supplier Part Number 1=445-6894-1-ND, TempCo=X7R, Tolerance_%=10, Value1="0.2162 ohm", Value2=50V, ValueDisplayed=0.015µF
C45 C48 C53: "CAP, CERM, 10 µF, 10 V,+/- 20%, X7R, 0603", Cap_Case=0603, Manufacturer=MuRata, Supplier Part Number 1=81-GRM188Z71A106MA3D, TempCo=X7R, Tolerance_%=20, Value2=10V, ValueDisplayed=10µF
C50: "CAP, CERM, 1 µF, 6.3 V,+/- 20%, X7R, 0402", Cap_Case=0402, Manufacturer=MuRata, Supplier Part Number 1=490-9665-1-ND, TempCo=X7R, Tolerance_%=20, Value2=6.3V, ValueDisplayed=1µF
C51: "CAP, CERM, 0.022 µF, 6.3 V, +/- 10%, X7R, 0402", Cap_Case=0402, Manufacturer=MuRata, Supplier Part Number 1=GRM155R70J223KA01D-ND, TempCo=X7R, Tolerance_%=10, Value1=Unknown, Value2=6.3V, ValueDisplayed=0.022µF
C56 C57 C58: library part CMP-0006629-2, "CAP, CERM, 0.1 uF, 10 V, +/- 10%, X7R, 0402", Cap_Case=0402, Manufacturer=MuRata, Supplier Part Number 1=GRM155R71A104KA01D-ND, TempCo=X7R, Tolerance_%=10%, Value1=Unknown, Value2=10V, ValueDisplayed=0.1uF
FID1 FID2 FID3 FID4 FID5 FID6: "Fiducial mark.  There is nothing to buy or mount.", Manufacturer=N/A
J1: "Straight Plug PCB", Alternate Manufacturer=-, Manufacturer=Rosenberger
L1: "Inductor, Shielded, Composite, 3.3 µH, 1.05 A, 0.21 ohm, SMD", Manufacturer=Coilcraft, Value1="0.21 ohm", Value2=1.05A, ValueDisplayed=3.3µH
L2 L3 L4: "Ferrite Bead, 1500 ohm @ 100 MHz, 0.5 A, 0603", Manufacturer=MuRata, Supplier Part Number 1=490-5216-1-ND, Value1="0.5 ohm", Value2=0.5A
L5: "Inductor, Wirewound, Ferrite, 10 µH, 0.81 A, 0.288 ohm, AEC-Q200 Grade 1, SMD", Manufacturer=MuRata, Supplier Part Number 1=81-LQH3NPZ100MJRL, Value1="0.288 ohm", Value2=0.81A, ValueDisplayed=10µH
L6: "Ferrite Bead, 1000 ohm @ 100 MHz, 0.4 A, 0603", Manufacturer=MuRata, Supplier Part Number 1=490-1015-1-ND, Value1="0.5 ohm", Value2=0.4A
L7 L8: library part CMP-0058761-1, "Inductor, Multilayer, Ferrite, 2.2 uH, 1.2 A, 0.11 ohm, SMD", Manufacturer=MuRata, Supplier Part Number 1=490-7786-1-ND, Value1="0.11 ohm", Value2=1.2A, ValueDisplayed=2.2uH
L9 L10 L11: "Ferrite Bead, 1000 ohm @ 100 MHz, 0.35 A, 0402", Manufacturer=MuRata, Supplier Part Number 1=490-5442-1-ND, Value1="0.49 ohm", Value2=0.35A
LH1: "Sunex Lens Holder", Manufacturer="Sunex Inc."
R1: "RES, 4.02 k, 1%, 0.1 W, 0603", Manufacturer=Vishay-Dale, Power_W=0.1, Supplier Part Number 1=541-4.02KHCT-ND, TempCo="100 ppm/C", Tolerance_%=1, Value1=1%, Value2=0.1W, Value_Code=4k02, ValueDisplayed=4.02k
R2: "RES, 0 ohm, 5%, 0.063W, 0402", Manufacturer=Vishay-Dale, Power_W=0.063, Supplier Part Number 1=541-0.0JCT-ND, TempCo="200 ppm/C", Tolerance_%=5, Value1=5%, Value2=0.063W, Value_Code=0000
R8 R9: "RES, 1.5 k, 5%, 0.063 W, 0402", Manufacturer=Vishay-Dale, Power_W=0.063, Supplier Part Number 1=541-1.5KJCT-ND, TempCo="200 ppm/C", Tolerance_%=5, Value1=5%, Value2=0.063W, Value_Code=1k50, ValueDisplayed=1.5k
R10 R13: "RES, 10k ohm, 5%, 0.063W, 0402", Manufacturer=Vishay-Dale, Power_W=0.063, Supplier Part Number 1=71-CRCW0402J-10K-E3, TempCo="200 ppm/C", Tolerance_%=5, Value1=5%, Value2=0.063W, Value_Code=10k0
R11: "RES, 49.9 ohm, 1%, 0.063W, 0402", Manufacturer=Vishay-Dale, Power_W=0.063, Supplier Part Number 1=541-49.9LCT-ND, TempCo="100 ppm/C", Tolerance_%=1, Value1=1%, Value2=0.063W, Value_Code=49R9
R12: library part CRCW04020000Z0ED, "RES, 0, 5%, 0.063 W, 0402", Manufacturer=Vishay-Dale, Power_W=0.063, Supplier Part Number 1=541-0.0JCT-ND, TempCo="200 ppm/C", Tolerance_%=5, Value1=5%, Value2=0.063W, Value_Code=0000, ValueDisplayed=0
R14: "RES, 40.2 k, 1%, 0.063 W, 0402", Manufacturer=Vishay-Dale, Power_W=0.063, Supplier Part Number 1=541-40.2KLCT-ND, TempCo="100 ppm/C", Tolerance_%=1, Value1=1%, Value2=0.063W, Value_Code=40k2, ValueDisplayed=40.2k
R15: "RES, 402, 1%, 0.063 W, 0402", Manufacturer=Vishay-Dale, Power_W=0.063, Supplier Part Number 1=541-402LCT-ND, TempCo="100 ppm/C", Tolerance_%=1, Value1=1%, Value2=0.063W, Value_Code=402R, ValueDisplayed=402
R16 R18: library part CMP-0026162-2, "RES, 20.0 k, 1%, 0.063 W, AEC-Q200 Grade 0, 0402", Manufacturer=Vishay-Dale, Power_W=63mW, Supplier Part Number 1=541-20.0KLCT-ND, TempCo="100 ppm/C", Tolerance_%=1%, Value2=0.063W, Value_Code=20k0, ValueDisplayed=20.0k
R17: library part CMP-0024337-2, "RES, 556 k, 0.1%, 0.1 W, 0603", Manufacturer="Yageo America", Power_W=100mW, TempCo="25 ppm/C", Tolerance_%=0.1%, Value2=0.1W, Value_Code=556k
R19: library part CMP-0026813-1, "RES, 5.00 k, 0.1%, 0.05 W, 0402", Manufacturer=Vishay-Dale, Power_W=50mW, Supplier Part Number 1=541-1901-1-ND, TempCo="25 ppm/C", Tolerance_%=0.1%, Value2=0.05W, Value_Code=5k00, ValueDisplayed=5.00k
R20: library part CMP-0026789-1, "RES, 86.6 k, 0.1%, 0.063 W, AEC-Q200 Grade 0, 0402", Manufacturer=Panasonic, Power_W=63mW, Supplier Part Number 1=P86.6KDCCT-ND, TempCo="25 ppm/C", Tolerance_%=0.1%, Value2=0.063W, Value_Code=86k6, ValueDisplayed=86.6k
U1: "3V-17V 1A Automotive Step-Down Converters in 2x2SON, DSG0008A (WSON-8)", Alternate Manufacturer="Texas Instruments", Alternate PartNumber=TPS62162QDSGTQ1
U2: library part CMP-0074043-2, "Automotive 2.5V to 6V, 2.25MHz Fixed Frequency Dual (800mA/800mA) Buck Converter, DRC0010J (VSON-10)", Alternate Manufacturer="Texas Instruments"
U3: library part CMP-0066023-1, "250-mA Ultra-Low-Noise, Low-IQ LDO, DQN0004A (X2SON-4)", Alternate Manufacturer="Texas Instruments"
U4: library part CMP-0078540-1, "Diagonal 6.67mm (Type 1/2.7) CMOS Solid-sate Image Sensor with Square Pixel and RGGB Filter Array, BGA-96", Manufacturer=Sony
U5: library part CMP-0084098-1, "2MP MIPI CSI-2 FPD-Link III Serializer for 2MP/60fps Cameras and RADAR, RHB0032P (VQFN-32)", Alternate Manufacturer="Texas Instruments", Alternate PartNumber=DS90UB953TRHBTQ1, Operating Temperature Range="-40 to 105 C", Rating=Automotive
U6 U8: library part CMP-0067338-2, "High-Accuracy, Fixed-Threshold OV/UV Monitor for Automotive, DDC0006A (SOT-23-T-6)", Alternate Manufacturer="Texas Instruments"
U7: library part CMP-0084096-1, "Automotive, High-Voltage (18V) Window Comparator with Over- and Undervoltage Detection, DSE0006A (WSON-6)", Alternate Manufacturer="Texas Instruments", Operating Temperature Range="-40 to 125 C", Rating=Automotive
ZZ1 ZZ2 ZZ3: library part AssemblyNote, Alternate Manufacturer=-

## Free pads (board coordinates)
  round 60 hole 280 unplated: 0(397.64,1357.14)

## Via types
v1: diameter 10, hole 6, Layer 1 - Top Layer to Layer 6 - Bottom Layer, tented both sides, 88 vias
v2: diameter 20, hole 10, Layer 1 - Top Layer to Layer 6 - Bottom Layer, tented both sides, 26 vias
v3: diameter 19.68, hole 7.87, Layer 1 - Top Layer to Layer 6 - Bottom Layer, 10 vias
v4: diameter 19.68, hole 7.87, Layer 1 - Top Layer to Layer 6 - Bottom Layer, tented both sides, 6 vias
v5: diameter 15, hole 8, Layer 1 - Top Layer to Layer 6 - Bottom Layer, tented both sides, 6 vias
v6: diameter 12, hole 6, Layer 1 - Top Layer to Layer 6 - Bottom Layer, tented both sides, 1 vias

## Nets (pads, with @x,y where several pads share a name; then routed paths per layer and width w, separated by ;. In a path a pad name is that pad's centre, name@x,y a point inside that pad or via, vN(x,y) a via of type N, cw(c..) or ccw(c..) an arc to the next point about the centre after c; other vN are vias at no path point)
1V2: C8.1 C12.1 C13.1 C20.1 C21.1 C25.1 C26.1 C27.1 C31.1 C32.1 L7.2 U2.4 U4.A3 U4.C11 U4.D11 U4.G1 U4.H1 U4.H11 U4.J11 U4.K1 U4.K11 U4.L2 U8.3 | length 2471.7
  Layer 1 - Top Layer w8: U2.4@184.69,404.88 v1(187,381)
  Layer 3 - PWR w12: v1(220.86,506.2) 220.86,481 245.86,456 453,456 466,469 v1@501,469 ; v5(290,152) 428,152 456.81,180.81 456.81,290.03 457,290.21 457,332 456.62,363 456.62,392.12 458.99,394.49 502.73,438.23 v1@502.73,470.73
  Layer 4 - Signal w8: v2(29,512) 29,457 109.19,376.81 ; 109,376.62 113,372.62 113,373 ; 113,371.62 125.62,359 165,359 v1(187,381) ; v1(238,215) 283,170 410,170 423,183 v1(423,197)
  Layer 6 - Bottom Layer w5: v1(503,471) 503.09,471.09 503.09,506.09 ; 504,506.09 504,507
  Layer 6 - Bottom Layer w8: v2(29,707) U8.3@87.87,702.4 ; U4.A3@204.27,488.98 v1(220.86,506.2) ; v1@239,215 245.25,215 U4.C11@267.26,237.01
  Layer 6 - Bottom Layer w10: 504,507 U4.L2@517.47,520.47
  Layer 6 - Bottom Layer w12: v2(29,512) 67,557 C26.1@119,557 C27.1@149.5,563.5 ; C27.1@154,563 171.5,579 ; 169.56,577.06 171.5,579 ; v5(283,58) 290,71 v5(290,152) 290,228.25 U4.D11@298.76,237.01 ; C12.1@421.69,136 421.69,163.68 C13.1@423,165 v1(423,197) 423,235.27 U4.H11@424.74,237.01 ; U4.H1@424.74,551.97 U4.G1@393.24,551.97 366.21,579 171.5,579 ; U4.J11@456.24,237.01 467.66,225.59 467.66,214.34 ; C31.1@456.31,135 456.31,203 467.66,214.34 ; U4.K11@487.73,237.01 487.73,234.42 467.66,214.34 ; U4.K1@487.73,551.97 U4.L2@519.23,520.47 U4.L2@517.47,520.47
  Layer 6 - Bottom Layer w20: C12.1@421.69,136 422.69,135 C31.1@456.31,135 456.31,122.66 457.34,122.66 v5(472,108)
  other v2: 154,691 154,714
1V8: C9.1 C22.1 C23.1 C24.1 L8.2 L9.1 L10.1 L11.1 R16.2 R18.2 U2.1 U4.L3 U4.L4 U4.L7 U6.3 | length 1743.1
  Layer 1 - Top Layer w8: C9.1@123,665 129,671 v1(149,671) ; U2.1@125.63,404.88 126,378 v1@127.63,379.63 ; R18.2@368,434 345,434 338,427 ; 338,427 337.13,427 v1(317.19,407.05) 318.05,407.05 338,427
  Layer 3 - PWR w8: v1@126,378 138,390 138,406 ; v1(149,671) 149,627.5 110,588.5 110,472.82 109.79,472.6 109.79,434.21 138,406 ; v1(317.19,407.05) 305.32,395.19 148.81,395.19 138,406
  Layer 3 - PWR w12: v2(330,733) 361,702 475,702 518.73,658.27 518.73,529 530,517.73 530,452.45 518.73,441.18 518.73,358.27 549,328 v2(661.61,328)
  Layer 6 - Bottom Layer w8: U4.L7@519.23,362.99 v1@542,340.22
  Layer 6 - Bottom Layer w10: U4.L4@519.23,457.48 U4.L3@519.23,488.98
  Layer 6 - Bottom Layer w12: R16.2@268,676 293.4,701.4 303.87,701.4 v2@330,727.54 ; U4.L4@519.23,457.48 538.52,457.48 546,450 546,410.6 561.6,395 C23.1@609,395 C22.1@645,395 ; 647,342.61 C22.1@647,397 ; 648,341.61 v2(661.61,328)
  other v1: 542,337 126,377
2V9: C7.1 C10.1 C11.1 C14.1 C15.1 C16.1 C17.1 C18.1 C19.1 R17.2 U3.1 U4.C4 U4.C5 U4.C6 U4.C7 U4.C8 U4.C9 U4.E9 U4.G9 U4.H9 U4.J4 | length 2806
  Layer 1 - Top Layer w8: v1(315,286) 332.63,286 R17.2@340.81,294.19
  Layer 1 - Top Layer w12: U3.1@75.8,408.06 75.8,439.11 C7.1@78.69,442
  Layer 1 - Top Layer w15: C7.1@78.69,442 78.69,504.68 v2(84,510)
  Layer 3 - PWR w8: v1(122,331) 131,340 263,340 ; v1(268,131) 268,335 ; v1(311.59,430.39) 312.23,430.39 330.19,412.44 330.19,399.15 v1(290.64,359.61) 271.03,340 263,340 ; 351,320 v1(318,320) 303,335 268,335 ; v1(440,285) 405,320 353,320 v1(473,440) ; 263,340 268,335
  Layer 4 - Signal w8: v1(6,475) 6,462.75 21.42,447.33 90.31,374 117.31,347 222.53,347 v1(284.14,408.61) ; v1(132,110) 132,174 103,203 103,274 127,298 303,298 v1(315,286)
  Layer 6 - Bottom Layer w8: v1(6,475) 6.42,474.58 66.08,474.58 66.5,474.16 C11.1@82,474 ; v1(79,340) 83,315 C14.1@86,312 ; C15.1@119,312 v1@119,328 ; C17.1@261,166 268,159 v1(268,131) ; U4.C9@267.26,300 288.26,321 v1@318,321 ; U4.C8@267.26,331.5 v1@291,355.24 ; U4.C7@267.26,362.99 v1@287.01,362.99 ; U4.C6@267.26,394.49 269.49,394.49 v1@284.12,409.12 ; U4.C5@267.26,425.98 v1@283.24,410 ; U4.C4@267.26,457.48 284.52,457.48 v1@312,430 ; v1(315,286) U4.E9@330.25,298.25 ; U4.H9@424.74,303.26 U4.H9@424.74,300 v1(440,285) ; U4.J4@456.24,457.48 v1@473,440.72
  Layer 6 - Bottom Layer w10: U4.E9@330.25,298.25 356,324 369.24,324 U4.G9@393.24,300
  Layer 6 - Bottom Layer w12: v1(132,110) 132,146.22 142,156.22 C19.1@142,177 141.32,176.32 C18.1@114,176.32 84,146.32 84,115 124,75 212,75 242,105 C16.1@242,129 261,148 C17.1@261,166
  Layer 6 - Bottom Layer w15: C11.1@82,474 82,478.69 C10.1@108.32,505 103.32,510 v2(84,510) ; C14.1@86,312 C15.1@119,312
3V3: C5.1 C6.1 C56.1 C57.1 C58.1 R2.1 U2.2 U2.3 U2.7 U2.9 U3.3 U3.4 U6.4 U6.5 U7.2 U8.4 U8.5 | length 1116.6
  Layer 1 - Top Layer w8: U2.9@145.32,515.12 v1(147.32,538) ; U2.7@186.69,515.12 187,515.43 v1(187,538) ; R2.1@308,380 302,380 302,373 C58.1@335,340 352,340 357,345 U7.2@364,345
  Layer 4 - Signal w8: 75.19,538 v1(147.32,538) v1(187,538) ; 75.19,539.09 74.09,539.09 ; v1(148,373) 148,392.19 60,480.19 60,525 74.09,539.09 ; v1(201,734) 201,666 ; v1(384,725) 363.81,725 341.21,702.4 237.4,702.4 201,666 ; 74.09,539.09 201,666
  Layer 6 - Bottom Layer w8: U6.4@409.13,701.4 U6.4@410.13,702.4
  Layer 6 - Bottom Layer w10: v1(201,734) 201,710.54 203.13,708.4 U8.5@203.13,671 ; U8.5@203.13,665 237,665 C57.1@239,665 ; v1(384,725) 400.6,708.4 409.13,708.4 409.13,701.4 U6.5@409.13,671 ; U6.4@410.13,702.4 410.73,703 443,703
ANALOG_RAIL_MON: R18.1 U5.28 U7.1 U7.6 | length 1135
  Layer 1 - Top Layer w8: v1(340,360) 345.81,360 350.5,364.68 U7.1@368.59,364.68 ; U7.6@416.62,364.68 U7.1@368.59,364.68 ; U5.28@592.84,680.49 v1(593,704) ; R18.1@368,393.24 368,365.28 U7.1@368.59,364.68 ; R18.1@368,393.24 368,394 366.81,395.19 365.31,393.68 365.75,393.24 R18.1@368,393.24
  Layer 5 - Signal/Gnd w8: v1(340,360) 324.87,375.13 236.13,375.13 196.25,415 129.65,415 113,431.65 113,596 241,724 291.03,724 303.03,712 460,712 461,711 485,735 585,735 593,727 v1@593,703
CSI0_CLK_N: U4.D2 U5.6 | length 477
  Layer 1 - Top Layer w8: v1@464.2,570.2 478.4,556 488.04,556 U5.6@488.51,556.47
  Layer 5 - Signal/Gnd w5: v1@315,504.23 v1(315,504) 310,504 307.23,506.77 307.23,512.23 314,517 318.86,517 324.5,511.36 324.5,495.09 341.59,478 345,478 350,473 350,465.7 336,451.7 336,420.86 338.93,417.93 346.86,410 373.14,410 422,458.86 424.93,461.79 424.93,506.07 422,509 405,526 405,542 438.5,575.5 460.5,575.5 v1(465,571)
  Layer 6 - Bottom Layer w8: U4.D2@298.76,520.47 v1@315,504.23
CSI0_CLK_P: U4.D1 U5.5 | length 476.2
  Layer 1 - Top Layer w8: v1@466.03,591 480.87,576.16 U5.5@488.51,576.16
  Layer 5 - Signal/Gnd w5: v1(315,536) 315,543 317,545 322,545 326,541 326,525 334.5,516.5 334.5,499.24 345.74,488 349.14,488 360,477.14 360,461.56 346,447.56 346,425 351,420 369,420 414.93,465.93 414.93,501.93 397.93,518.93 395,521.86 395,546.14 397.93,549.07 434.36,585.5 460.5,585.5 v1(465,590)
  Layer 6 - Bottom Layer w8: U4.D1@298.76,551.97 v1@314.72,536
CSI0_D0_N: U4.E2 U5.4 | length 456.1
  Layer 1 - Top Layer w8: 468,606 478.16,595.84 U5.4@488.51,595.84
  Layer 5 - Signal/Gnd w5: v1@346,507.86 366,527.86 366,548.72 378.28,561 392.69,561 404,572.31 404,591.14 393.14,602 334,602 320.14,615.86 320.14,626.14 328,634 333.79,634 349.86,617.93 364.93,617.93 382,635 403.93,635 409.07,629.86 409.07,616.79 417.86,608 421.86,604 436,604 447,615 460,615 v1(465,610)
  Layer 6 - Bottom Layer w8: U4.E2@330.25,520.47 v1@346,504.72
  other v1: 346,504
CSI0_D0_P: U4.E1 U5.3 | length 484.7
  Layer 1 - Top Layer w8: v1@466.63,630 481.1,615.53 U5.3@488.51,615.53
  Layer 5 - Signal/Gnd w5: v1@345,537 340,537 337,534 337,526.73 341.73,522 346,522 356,532 356,552.86 374.14,571 388.54,571 394,576.46 394,587 389,592 329.86,592 326.93,594.93 310.14,611.72 310.14,630.28 323.86,644 337.93,644 354,627.93 360.79,627.93 377.86,645 410,645 422,633 422,618 426,614 431.86,614 442.86,625 460,625 v1(465,630)
  Layer 6 - Bottom Layer w8: U4.E1@330.25,551.97 v1@345,537.22
  other v1: 346,536
CSI0_D1_N: U4.C2 U5.2 | length 480.7
  Layer 1 - Top Layer w8: v1(465,650) 479.79,635.21 U5.2@488.51,635.21
  Layer 5 - Signal/Gnd w5: v1(283,504) 283,509.93 288.07,515 292.14,515 303,525.86 303,594.14 276.14,621 245,621 235,631 235,637 252.5,654.5 460.5,654.5 v1(465,650)
  Layer 6 - Bottom Layer w8: U4.C2@267.26,520.47 v1@282.73,505
CSI0_D1_P: U4.C1 U5.1 | length 476.3
  Layer 1 - Top Layer w8: v1(465,669) 468.63,669 482.73,654.9 U5.1@488.51,654.9
  Layer 5 - Signal/Gnd w5: v1(283,536) 283,530 285.5,527.5 290.5,527.5 293,530 293,585.86 267.86,611 240.86,611 225,626.86 225,641.14 248.36,664.5 460.5,664.5 v1(465,669)
  Layer 6 - Bottom Layer w8: U4.C1@267.26,551.97 v1@283,536.23
CSI0_D2_N: U4.F2 U5.32 | length 486.4
  Layer 1 - Top Layer w8: v1(514,704) 514,680.59 U5.32@514.1,680.49
  Layer 4 - Signal w5: v1(378,504) 378,511 383,516 394.64,516 399.14,516 407.07,523.93 449,565.86 449,589.64 446.07,592.57 435.56,603.08 432.63,606.01 407.15,606.01 391.07,589.93 381,589.93 376.5,594.43 376.5,606.63 393.87,624 418.08,624 438.94,644.86 438.94,669.07 486.94,717.07 515.93,717.07 519,714 519,708 514.5,703.5 v1@514,703
  Layer 6 - Bottom Layer w8: U4.F2@361.75,520.47 v1@377,505.22
CSI0_D2_P: U4.F1 U5.31 | length 487.3
  Layer 1 - Top Layer w8: U5.31@533.79,680.49 534,680.7 v1(534,704)
  Layer 4 - Signal w5: v1(378,536) 405,536 436,567 436,588.5 428.49,596.01 411.29,596.01 395.21,579.93 376.86,579.93 366.5,590.29 366.5,610.77 389.73,634 413.94,634 428.94,649 428.94,673.21 482.8,727.07 520.07,727.07 529,718.14 529,708 533.5,703.5 v1@534,703
  Layer 6 - Bottom Layer w8: U4.F1@361.75,551.97 v1@377,536.72
CSI0_D3_N: U4.B2 U5.30 | length 485.3
  Layer 1 - Top Layer w8: v1(553,704) 553,680.96 U5.30@553.47,680.49
  Layer 4 - Signal w5: v1@252,506 266.87,520.87 266.87,536.13 282.14,551.41 294.41,551.41 484,741 534.57,741 558,717.57 558,708 553.5,703.5 v1@553,703
  Layer 6 - Bottom Layer w8: U4.B2@235.76,520.47 v1@252,504.24
  other v1: 252,504
CSI0_D3_P: U4.B1 U5.29 | length 483.3
  Layer 1 - Top Layer w8: v1(573,704) 573,680.65 U5.29@573.16,680.49
  Layer 4 - Signal w5: v1(251,537) 253.59,537 279.59,563 291.86,563 479.86,751 538.71,751 568,721.71 568,708 572.5,703.5 v1@573,703
  Layer 6 - Bottom Layer w8: U4.B1@235.76,551.97 v1@250.73,537
DIGITAL_RAIL_MON: R16.1 U5.27 U6.1 U6.6 U8.1 U8.6 | length 950.2
  Layer 1 - Top Layer w8: v1(612,704) 612,681.02 U5.27@612.53,680.49
  Layer 5 - Signal/Gnd w8: v1(127,633) 152,658 154.38,658 162,665.62 162,668 255,761 383.62,761 415.62,729 455,729 475,749 593,749 612,730 v1@612,703
  Layer 6 - Bottom Layer w8: R16.1@268,636 277.4,626.6 U6.6@412.13,626.6
  Layer 6 - Bottom Layer w10: U8.1@94.87,633.6 U8.6@209.13,633.6 ; U8.6@203.13,627.6 U8.6@209.13,633.6 ; R16.1@268,636 211.54,636 U8.6@209.13,633.6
